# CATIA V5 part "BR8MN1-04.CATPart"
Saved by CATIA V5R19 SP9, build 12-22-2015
Part number: BR8MN1-04
Definition: design
Nomenclature: BR8MN1-04
Source: Unknown
Bounding box of the stored display mesh (mm): x -4.6 to 7.9, y 0 to 12, z 0 to 20.32
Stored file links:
  Z:\charly_robot\BR8MN1-04.CATPart
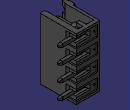
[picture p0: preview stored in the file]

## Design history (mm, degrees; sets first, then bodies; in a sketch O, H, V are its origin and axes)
AxisSystem1: origin (0, 0, 0), X (1, 0, 0), Y (0, 1, 0), Z (0, 0, 1)
Body1 "MANIFOLD_SOLID_BREP #177283" (main body)
  Solid1: solid without history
